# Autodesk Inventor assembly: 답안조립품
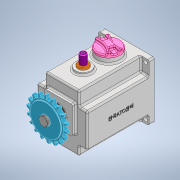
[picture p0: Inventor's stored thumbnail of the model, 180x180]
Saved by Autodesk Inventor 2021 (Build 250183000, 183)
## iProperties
Created: 2022-08
Part Number: 답안조립품
Document SubType Name: Assembly
Designer: Owner
Author: Owner
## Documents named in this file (16)
- C:\Users\Owner\Desktop\720810V1011\답안조립품.iam
- C:\Users\Owner\Desktop\720810V1011\본체.ipt
- C:\Users\Owner\Desktop\720810V1011\베어링 608.ipt
- C:\Users\Owner\Desktop\720810V1011\베어링 6003.ipt
- C:\Users\Owner\Desktop\720810V1011\메인 축.ipt
- C:\Users\Owner\Desktop\720810V1011\커버.ipt
- C:\Users\Owner\Desktop\720810V1011\오일 실 8 x 22 x 7.ipt
- C:\Users\Owner\Desktop\720810V1011\서브 축.ipt
- C:\Users\Owner\Desktop\720810V1011\오일 실 17 x 32 x 8.ipt
- C:\Users\Owner\Desktop\720810V1011\부시.ipt
- C:\Users\Owner\Desktop\720810V1011\슬라이더.ipt
- C:\Users\Owner\Desktop\720810V1011\스프로킷.ipt
- C:\Users\Owner\Desktop\720810V1011\키 5 x 5.ipt
- C:\Users\Owner\Desktop\720810V1011\멈춤나사 M3.ipt
- C:\Users\Owner\Desktop\720810V1011\상부 캡.ipt
- C:\Users\Owner\Desktop\720810V1011\볼트 M4 x 10.ipt
